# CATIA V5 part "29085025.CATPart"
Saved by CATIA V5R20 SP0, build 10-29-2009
Part number: 29085025
Definition: NONE
Nomenclature: 29085025
Source: Unknown
Description: 29085025
Bounding box of the stored display mesh (mm): x -12.5 to 44.548, y -56.5 to 91.048, z -46.5 to 46.5
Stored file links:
  C:\Users\Utente\Desktop\IO LAVORO\3D X SITO CF\X SITO\PLASTICA\RF1\29085025.CATPart
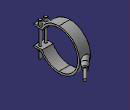
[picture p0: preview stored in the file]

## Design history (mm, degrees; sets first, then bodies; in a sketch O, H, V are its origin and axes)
Body1 "29085025" (main body)
  Solid1: solid without history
